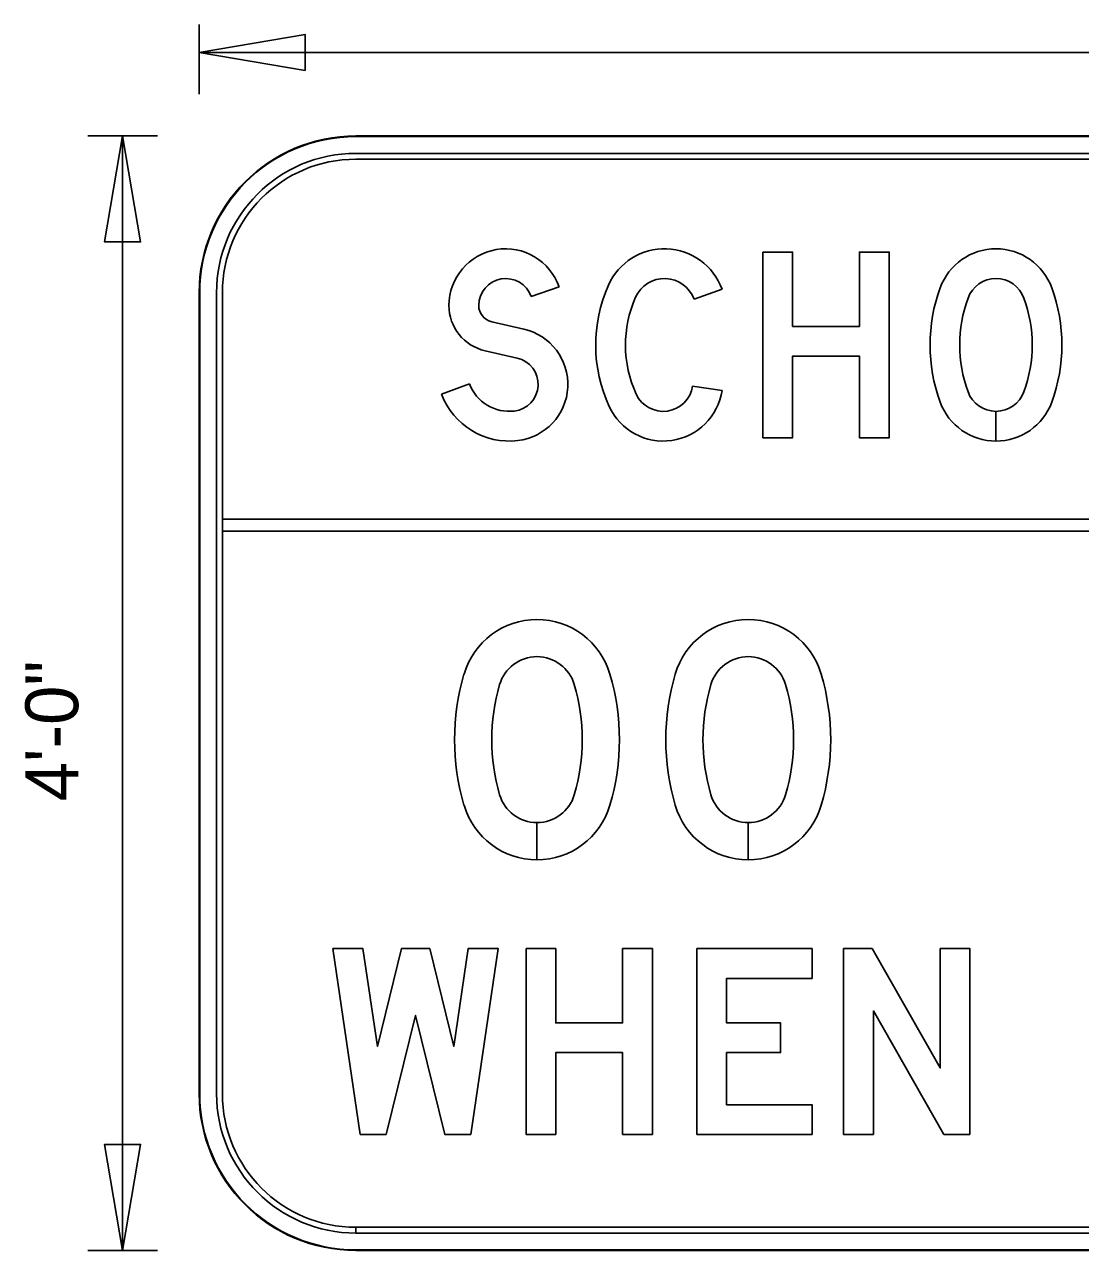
# Model space of a CAD drawing. Extents: x 0 to 770, y 0 to 495.
# Drawn here: x 393.2 to 463.1, y 393.4 to 474.6 of the extents above; entities that cross this region are included whole.
import ezdxf

# ---------------------------------------------------------------- set-up
doc = ezdxf.new("R2010")
doc.units = 0
for name, color, linetype in [('Dimension', 7, 'Continuous'), ('GSBWFill', 7, 'Continuous'), ('GSColorFill', 7, 'Continuous'), ('GSDims', 7, 'Continuous'), ('GSOutline', 7, 'Continuous'), ('TextStructures', 7, 'Continuous')]:
    doc.layers.add(name, color=color, linetype=linetype)

msp = doc.modelspace()

# ---------------------------------------------------------------- linework, layer by layer
at = {"layer": 'Dimension'}
for points in [[(404.78, 472.741), (411.797, 471.552), (411.797, 473.93)], [(399.709, 467.209), (398.52, 460.192), (400.898, 460.192)], [(399.709, 393.443), (400.898, 400.46), (398.52, 400.46)]]:
    msp.add_lwpolyline(points, close=True, dxfattribs=at)
at = {"layer": 'GSBWFill'}
for p, q in [((541.937, 467.209), (415.154, 467.209)), ((541.937, 466.056), (415.154, 466.056)), ((415.154, 465.672), (541.937, 465.672)), ((404.78, 456.835), (404.78, 403.817)), ((405.933, 456.835), (405.933, 403.817)), ((406.317, 403.817), (406.317, 456.835)), ((426.75, 456.575), (428.608, 457.22)), ((439.389, 457.072), (437.54, 456.398)), ((426.266, 454.429), (424.144, 454.911)), ((423.708, 452.993), (425.83, 452.511)), ((422.665, 450.813), (420.824, 450.12)), ((437.443, 450.659), (439.389, 450.368)), ((457.523, 447.015), (457.523, 448.982)), ((457.523, 448.982), (457.523, 447.015)), ((550.774, 441.852), (406.317, 441.852)), ((406.317, 441.852), (406.317, 441.053)), ((406.317, 441.053), (550.774, 441.053)), ((427.141, 421.758), (427.141, 419.3)), ((427.141, 419.3), (427.141, 421.758)), ((441.125, 419.3), (441.125, 421.758)), ((441.126, 421.758), (441.126, 419.3)), ((415.154, 394.596), (415.154, 394.98)), ((541.937, 394.98), (415.158, 394.98)), ((415.158, 394.98), (415.158, 394.596)), ((415.158, 394.596), (541.937, 394.596)), ((415.154, 393.443), (541.937, 393.443))]:
    msp.add_line(p, q, dxfattribs=at)
for points in [[(442.093, 459.525), (444.06, 459.525), (444.06, 454.607), (448.486, 454.607), (448.486, 459.525), (450.453, 459.525), (450.453, 447.23), (448.486, 447.23), (448.486, 452.64), (444.06, 452.64), (444.06, 447.23), (442.093, 447.23)], [(417.167, 401.127), (419.103, 408.996), (421.04, 401.127), (422.761, 401.127), (424.574, 413.421), (422.586, 413.421), (421.632, 406.953), (420.04, 413.421), (418.167, 413.421), (416.575, 406.953), (415.621, 413.421), (413.632, 413.421), (415.446, 401.127)], [(426.418, 413.421), (428.385, 413.421), (428.385, 408.504), (432.811, 408.504), (432.811, 413.421), (434.778, 413.421), (434.778, 401.127), (432.811, 401.127), (432.811, 406.537), (428.385, 406.537), (428.385, 401.127), (426.418, 401.127)], [(445.351, 411.454), (439.696, 411.454), (439.696, 408.504), (443.271, 408.504), (443.271, 406.537), (439.696, 406.537), (439.696, 403.094), (445.351, 403.094), (445.351, 401.127), (437.729, 401.127), (437.729, 413.421), (445.351, 413.421)], [(455.801, 401.127), (455.801, 413.421), (453.834, 413.421), (453.834, 405.522), (449.32, 413.421), (447.441, 413.421), (447.441, 401.127), (449.408, 401.127), (449.408, 409.303), (454.08, 401.127)]]:
    msp.add_lwpolyline(points, close=True, dxfattribs=at)
for centre, radius, start, end in [((415.154, 456.835), 10.373, 90, 180), ((415.154, 456.835), 9.221, 90, 180), ((415.154, 456.835), 8.836, 90, 180), ((425.066, 455.99), 3.75, 19.13948, 180), ((425.066, 455.99), 1.783, 19.13948, 180), ((424.39, 455.99), 3.074, 180, 257.19149), ((424.39, 455.99), 1.106, 180, 257.19149), ((425.435, 450.772), 3.75, 276.78539, 77.19149), ((425.435, 450.772), 1.783, 276.78539, 77.19149), ((425.311, 451.81), 2.828, 200.64423, 276.78539), ((425.311, 451.81), 4.795, 200.64423, 276.78539), ((427.141, 430.17), 5.035, 16.40247, 163.59753), ((441.125, 430.17), 5.035, 16.40247, 163.59753), ((427.141, 430.17), 2.576, 16.40247, 163.59753), ((441.125, 430.17), 2.576, 16.40247, 163.59753), ((437.053, 427.252), 15.368, 163.59753, 196.40247), ((437.053, 427.252), 12.909, 163.59753, 196.40247), ((417.228, 427.252), 12.909, 343.59753, 16.40247), ((417.228, 427.252), 15.368, 343.59753, 16.40247), ((451.037, 427.252), 15.368, 163.59753, 196.40247), ((451.037, 427.252), 12.909, 163.59753, 196.40247), ((431.213, 427.252), 12.909, 343.59753, 16.40247), ((431.213, 427.252), 15.368, 343.59753, 16.40247), ((427.141, 424.335), 2.576, 196.40247, 270), ((427.141, 424.335), 2.576, 270.01709, 343.59753), ((441.125, 424.335), 2.576, 196.40247, 270), ((441.125, 424.335), 2.576, 270.01709, 343.59753), ((427.141, 424.335), 5.035, 196.40247, 270), ((427.141, 424.335), 5.035, 270.00874, 343.59753), ((441.125, 424.335), 5.035, 196.40247, 270), ((441.125, 424.335), 5.035, 270.00874, 343.59753), ((415.154, 403.817), 10.373, 180, 270), ((415.154, 403.817), 9.221, 180, 270), ((415.154, 403.817), 8.836, 180, 270)]:
    msp.add_arc(centre, radius, start, end, dxfattribs=at)
for centre, major_axis, start_param, end_param in [((435.577, 455.683), (0, 4.057), 5.061866, 7.434148), ((457.523, 455.806), (0, 3.934), 5.063177, 7.503193), ((435.577, 455.683), (0, 2.09), 5.061866, 7.434148), ((457.523, 455.806), (0, 1.967), 5.063177, 7.503193), ((440.741, 453.378), (0, 9.712), 1.150963, 2.004476), ((464.158, 453.378), (0, 11), 1.220008, 1.921585), ((450.887, 453.378), (0, 11), 4.361601, 5.063177), ((440.741, 453.378), (0, 7.745), 1.150963, 2.004476), ((464.158, 453.378), (0, 9.033), 1.220008, 1.921585), ((450.887, 453.378), (0, 9.033), 4.361601, 5.063177), ((435.498, 450.949), (0, 3.934), 2.004476, 4.564141), ((435.498, 450.949), (0, 1.967), 2.004476, 4.564141), ((457.523, 450.949), (0, 3.934), 1.921585, 3.141593), ((457.523, 450.949), (0, 1.967), 1.921585, 3.141593), ((457.523, 450.949), (0, 1.967), 3.141905, 4.361601), ((457.523, 450.949), (0, 3.934), 3.141749, 4.361601)]:
    msp.add_ellipse(centre, major_axis=major_axis, ratio=0.999993, start_param=start_param, end_param=end_param, dxfattribs=at)
at = {"layer": 'GSColorFill'}
for p, q in [((541.937, 467.209), (415.154, 467.209)), ((541.937, 467.209), (415.154, 467.209)), ((415.154, 467.17), (541.937, 467.17)), ((541.937, 466.056), (415.154, 466.056)), ((415.154, 465.672), (541.937, 465.672)), ((404.78, 456.835), (404.78, 403.817)), ((404.78, 456.835), (404.78, 403.817)), ((404.819, 403.817), (404.819, 456.835)), ((405.933, 456.835), (405.933, 403.817)), ((406.317, 403.817), (406.317, 456.835)), ((426.75, 456.575), (428.608, 457.22)), ((439.389, 457.072), (437.54, 456.398)), ((426.266, 454.429), (424.144, 454.911)), ((423.708, 452.993), (425.83, 452.511)), ((422.665, 450.813), (420.824, 450.12)), ((437.443, 450.659), (439.389, 450.368)), ((457.523, 447.015), (457.523, 448.982)), ((457.523, 448.982), (457.523, 447.015)), ((550.774, 441.852), (406.317, 441.852)), ((406.317, 441.852), (406.317, 441.053)), ((406.317, 441.053), (550.774, 441.053)), ((427.141, 421.758), (427.141, 419.3)), ((427.141, 419.3), (427.141, 421.758)), ((441.125, 419.3), (441.125, 421.758)), ((441.126, 421.758), (441.126, 419.3)), ((415.154, 394.596), (415.154, 394.98)), ((541.937, 394.98), (415.158, 394.98)), ((415.158, 394.98), (415.158, 394.596)), ((415.158, 394.596), (541.937, 394.596)), ((415.154, 393.443), (415.154, 393.482)), ((541.937, 393.482), (415.154, 393.482)), ((415.154, 393.482), (415.154, 393.443)), ((415.154, 393.443), (541.937, 393.443)), ((415.154, 393.443), (541.937, 393.443))]:
    msp.add_line(p, q, dxfattribs=at)
for points in [[(442.093, 459.525), (444.06, 459.525), (444.06, 454.607), (448.486, 454.607), (448.486, 459.525), (450.453, 459.525), (450.453, 447.23), (448.486, 447.23), (448.486, 452.64), (444.06, 452.64), (444.06, 447.23), (442.093, 447.23)], [(417.167, 401.127), (419.103, 408.996), (421.04, 401.127), (422.761, 401.127), (424.574, 413.421), (422.586, 413.421), (421.632, 406.953), (420.04, 413.421), (418.167, 413.421), (416.575, 406.953), (415.621, 413.421), (413.632, 413.421), (415.446, 401.127)], [(426.418, 413.421), (428.385, 413.421), (428.385, 408.504), (432.811, 408.504), (432.811, 413.421), (434.778, 413.421), (434.778, 401.127), (432.811, 401.127), (432.811, 406.537), (428.385, 406.537), (428.385, 401.127), (426.418, 401.127)], [(445.351, 411.454), (439.696, 411.454), (439.696, 408.504), (443.271, 408.504), (443.271, 406.537), (439.696, 406.537), (439.696, 403.094), (445.351, 403.094), (445.351, 401.127), (437.729, 401.127), (437.729, 413.421), (445.351, 413.421)], [(455.801, 401.127), (455.801, 413.421), (453.834, 413.421), (453.834, 405.522), (449.32, 413.421), (447.441, 413.421), (447.441, 401.127), (449.408, 401.127), (449.408, 409.303), (454.08, 401.127)]]:
    msp.add_lwpolyline(points, close=True, dxfattribs=at)
for centre, radius, start, end in [((415.154, 456.835), 10.373, 90, 180), ((415.154, 456.835), 10.373, 90, 180), ((415.154, 456.835), 10.335, 90, 180), ((415.154, 456.835), 9.221, 90, 180), ((415.154, 456.835), 8.836, 90, 180), ((425.066, 455.99), 3.75, 19.13948, 180), ((425.066, 455.99), 1.783, 19.13948, 180), ((424.39, 455.99), 3.074, 180, 257.19149), ((424.39, 455.99), 1.106, 180, 257.19149), ((425.435, 450.772), 3.75, 276.78539, 77.19149), ((425.435, 450.772), 1.783, 276.78539, 77.19149), ((425.311, 451.81), 2.828, 200.64423, 276.78539), ((425.311, 451.81), 4.795, 200.64423, 276.78539), ((427.141, 430.17), 5.035, 16.40247, 163.59753), ((441.125, 430.17), 5.035, 16.40247, 163.59753), ((427.141, 430.17), 2.576, 16.40247, 163.59753), ((441.125, 430.17), 2.576, 16.40247, 163.59753), ((437.053, 427.252), 15.368, 163.59753, 196.40247), ((437.053, 427.252), 12.909, 163.59753, 196.40247), ((417.228, 427.252), 12.909, 343.59753, 16.40247), ((417.228, 427.252), 15.368, 343.59753, 16.40247), ((451.037, 427.252), 15.368, 163.59753, 196.40247), ((451.037, 427.252), 12.909, 163.59753, 196.40247), ((431.213, 427.252), 12.909, 343.59753, 16.40247), ((431.213, 427.252), 15.368, 343.59753, 16.40247), ((427.141, 424.335), 2.576, 196.40247, 270), ((427.141, 424.335), 2.576, 270.01709, 343.59753), ((441.125, 424.335), 2.576, 196.40247, 270), ((441.125, 424.335), 2.576, 270.01709, 343.59753), ((427.141, 424.335), 5.035, 196.40247, 270), ((427.141, 424.335), 5.035, 270.00874, 343.59753), ((441.125, 424.335), 5.035, 196.40247, 270), ((441.125, 424.335), 5.035, 270.00874, 343.59753), ((415.154, 403.817), 10.373, 180, 270), ((415.154, 403.817), 10.373, 180, 270), ((415.154, 403.817), 10.335, 180, 270), ((415.154, 403.817), 9.221, 180, 270), ((415.154, 403.817), 8.836, 180, 270)]:
    msp.add_arc(centre, radius, start, end, dxfattribs=at)
for centre, major_axis, start_param, end_param in [((435.577, 455.683), (0, 4.057), 5.061866, 7.434148), ((457.523, 455.806), (0, 3.934), 5.063177, 7.503193), ((435.577, 455.683), (0, 2.09), 5.061866, 7.434148), ((457.523, 455.806), (0, 1.967), 5.063177, 7.503193), ((440.741, 453.378), (0, 9.712), 1.150963, 2.004476), ((464.158, 453.378), (0, 11), 1.220008, 1.921585), ((450.887, 453.378), (0, 11), 4.361601, 5.063177), ((440.741, 453.378), (0, 7.745), 1.150963, 2.004476), ((464.158, 453.378), (0, 9.033), 1.220008, 1.921585), ((450.887, 453.378), (0, 9.033), 4.361601, 5.063177), ((435.498, 450.949), (0, 3.934), 2.004476, 4.564141), ((435.498, 450.949), (0, 1.967), 2.004476, 4.564141), ((457.523, 450.949), (0, 3.934), 1.921585, 3.141593), ((457.523, 450.949), (0, 1.967), 1.921585, 3.141593), ((457.523, 450.949), (0, 1.967), 3.141905, 4.361601), ((457.523, 450.949), (0, 3.934), 3.141749, 4.361601)]:
    msp.add_ellipse(centre, major_axis=major_axis, ratio=0.999993, start_param=start_param, end_param=end_param, dxfattribs=at)
at = {"layer": 'GSDims'}
for p, q in [((404.78, 469.975), (404.78, 474.585)), ((404.78, 472.741), (552.311, 472.741)), ((402.014, 467.209), (397.404, 467.209)), ((399.709, 393.443), (399.709, 467.209)), ((402.014, 393.443), (397.404, 393.443))]:
    msp.add_line(p, q, dxfattribs=at)
at = {"layer": 'GSOutline'}
for p, q in [((541.937, 467.209), (415.154, 467.209)), ((541.937, 466.056), (415.154, 466.056)), ((541.937, 465.672), (415.154, 465.672)), ((404.78, 456.835), (404.78, 403.817)), ((405.933, 456.835), (405.933, 403.817)), ((406.317, 456.835), (406.317, 403.817)), ((426.75, 456.575), (428.608, 457.22)), ((439.389, 457.072), (437.54, 456.398)), ((426.266, 454.429), (424.144, 454.911)), ((423.708, 452.993), (425.83, 452.511)), ((422.665, 450.813), (420.824, 450.12)), ((437.443, 450.659), (439.389, 450.368)), ((550.774, 441.852), (406.317, 441.852)), ((406.317, 441.852), (406.317, 441.053)), ((406.317, 441.053), (550.774, 441.053)), ((415.154, 394.98), (541.937, 394.98)), ((415.154, 394.596), (541.937, 394.596)), ((415.154, 393.443), (541.937, 393.443))]:
    msp.add_line(p, q, dxfattribs=at)
for points in [[(442.093, 459.525), (444.06, 459.525), (444.06, 454.607), (448.486, 454.607), (448.486, 459.525), (450.453, 459.525), (450.453, 447.23), (448.486, 447.23), (448.486, 452.64), (444.06, 452.64), (444.06, 447.23), (442.093, 447.23)], [(417.167, 401.127), (419.103, 408.996), (421.04, 401.127), (422.761, 401.127), (424.574, 413.421), (422.586, 413.421), (421.632, 406.953), (420.04, 413.421), (418.167, 413.421), (416.575, 406.953), (415.621, 413.421), (413.632, 413.421), (415.446, 401.127)], [(426.418, 413.421), (428.385, 413.421), (428.385, 408.504), (432.811, 408.504), (432.811, 413.421), (434.778, 413.421), (434.778, 401.127), (432.811, 401.127), (432.811, 406.537), (428.385, 406.537), (428.385, 401.127), (426.418, 401.127)], [(445.351, 411.454), (439.696, 411.454), (439.696, 408.504), (443.271, 408.504), (443.271, 406.537), (439.696, 406.537), (439.696, 403.094), (445.351, 403.094), (445.351, 401.127), (437.729, 401.127), (437.729, 413.421), (445.351, 413.421)], [(455.801, 401.127), (455.801, 413.421), (453.834, 413.421), (453.834, 405.522), (449.32, 413.421), (447.441, 413.421), (447.441, 401.127), (449.408, 401.127), (449.408, 409.303), (454.08, 401.127)]]:
    msp.add_lwpolyline(points, close=True, dxfattribs=at)
for centre, radius, start, end in [((415.154, 456.835), 10.373, 90, 180), ((415.154, 456.835), 9.221, 90, 180), ((415.154, 456.835), 8.836, 90, 180), ((425.066, 455.99), 3.75, 19.13948, 180), ((425.066, 455.99), 1.783, 19.13948, 180), ((424.39, 455.99), 3.074, 180, 257.19149), ((424.39, 455.99), 1.106, 180, 257.19149), ((425.435, 450.772), 3.75, 276.78539, 77.19149), ((425.435, 450.772), 1.783, 276.78539, 77.19149), ((425.311, 451.81), 2.828, 200.64423, 276.78539), ((425.311, 451.81), 4.795, 200.64423, 276.78539), ((427.141, 430.17), 5.035, 16.40247, 163.59753), ((441.125, 430.17), 5.035, 16.40247, 163.59753), ((427.141, 430.17), 2.576, 16.40247, 163.59753), ((441.125, 430.17), 2.576, 16.40247, 163.59753), ((437.053, 427.252), 15.368, 163.59753, 196.40247), ((437.053, 427.252), 12.909, 163.59753, 196.40247), ((417.228, 427.252), 12.909, 343.59753, 16.40247), ((417.228, 427.252), 15.368, 343.59753, 16.40247), ((451.037, 427.252), 15.368, 163.59753, 196.40247), ((451.037, 427.252), 12.909, 163.59753, 196.40247), ((431.213, 427.252), 12.909, 343.59753, 16.40247), ((431.213, 427.252), 15.368, 343.59753, 16.40247), ((427.141, 424.335), 2.576, 196.40247, 343.59753), ((441.125, 424.335), 2.576, 196.40247, 343.59753), ((427.141, 424.335), 5.035, 196.40247, 343.59753), ((441.125, 424.335), 5.035, 196.40247, 343.59753), ((415.154, 403.817), 10.373, 180, 270), ((415.154, 403.817), 9.221, 180, 270), ((415.154, 403.817), 8.836, 180, 270)]:
    msp.add_arc(centre, radius, start, end, dxfattribs=at)
for centre, major_axis, start_param, end_param in [((435.577, 455.683), (0, 4.057), 5.061866, 7.434148), ((457.523, 455.806), (0, 3.934), 5.063177, 7.503193), ((435.577, 455.683), (0, 2.09), 5.061866, 7.434148), ((457.523, 455.806), (0, 1.967), 5.063177, 7.503193), ((440.741, 453.378), (0, 9.712), 1.150963, 2.004476), ((464.158, 453.378), (0, 11), 1.220008, 1.921585), ((450.887, 453.378), (0, 11), 4.361601, 5.063177), ((440.741, 453.378), (0, 7.745), 1.150963, 2.004476), ((464.158, 453.378), (0, 9.033), 1.220008, 1.921585), ((450.887, 453.378), (0, 9.033), 4.361601, 5.063177), ((435.498, 450.949), (0, 3.934), 2.004476, 4.564141), ((435.498, 450.949), (0, 1.967), 2.004476, 4.564141), ((457.523, 450.949), (0, 3.934), 1.921585, 4.361601), ((457.523, 450.949), (0, 1.967), 1.921585, 4.361601)]:
    msp.add_ellipse(centre, major_axis=major_axis, ratio=0.999993, start_param=start_param, end_param=end_param, dxfattribs=at)

# ---------------------------------------------------------------- texts
at = {"layer": 'TextStructures'}
msp.add_text('4\'-0"', height=3.5, rotation=90, dxfattribs=at).set_placement((396.773, 423.171))

doc.saveas('drawing.dxf')
